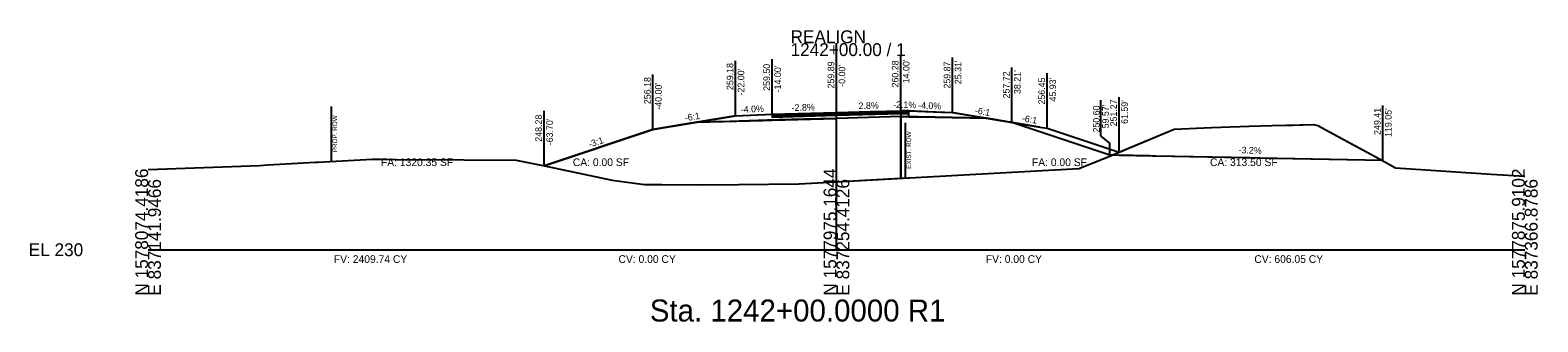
# Model space of a CAD drawing. Extents: x -26 to 6303, y -16 to 9563.
# Drawn here: x 1974.3 to 2302.8, y 1984.3 to 2047.8 of the extents above; entities that cross this region are included whole.
import ezdxf

# ---------------------------------------------------------------- set-up
doc = ezdxf.new("R2010")
doc.units = 0
for name, color, linetype in [('ASPHALT_19MM1', 7, 'Continuous'), ('ASPHALT_9_5MM1', 7, 'Continuous'), ('CONST_DCH', 7, 'Continuous'), ('CONST_LV3', 7, 'Continuous'), ('Draft_XS_Grid', 7, 'Continuous'), ('Draft_XS_Text', 7, 'Continuous'), ('DTM_P_FINISHED_GRADE', 7, 'Continuous'), ('DTM_P_FINISHED_GRADE2', 7, 'Continuous'), ('DTM_TEMP_DROP', 7, 'Continuous'), ('DTM_X_GROUND', 7, 'Continuous'), ('TRANS_EOP_PAVED', 7, 'Continuous'), ('TRANS_PAVED_SHOULDERS', 7, 'Continuous'), ('XS_CELL', 7, 'Continuous'), ('XS_M_SHAPES_EARTHWORK', 7, 'Continuous'), ('XS_P_ASPHALT', 7, 'Continuous'), ('XS_P_GROUND', 7, 'Continuous'), ('XS_P_ROW', 7, 'Continuous'), ('XS_P_SHOULDER', 7, 'Continuous'), ('XS_P_SUBGRADE_GRANULAR', 7, 'Continuous'), ('XS_P_TX_CLEARZONE', 7, 'Continuous'), ('XS_P_TX_FS_BS', 7, 'Continuous'), ('XS_SHEET_EW_TX_AREA', 7, 'Continuous'), ('XS_SHEET_EW_TX_VOLUME', 7, 'Continuous'), ('XS_X_ROW', 7, 'Continuous')]:
    doc.layers.add(name, color=color, linetype=linetype)

msp = doc.modelspace()

# ---------------------------------------------------------------- linework, layer by layer
at = {"layer": 'ASPHALT_19MM1'}
for points in [[(2136, 2029.17), (2136, 2028.9), (2150, 2029.29), (2150, 2029.29), (2164, 2029.68), (2164, 2029.68), (2164, 2029.95), (2164, 2029.95), (2164, 2029.95), (2150, 2029.56), (2150, 2029.56), (2136, 2029.17), (2136, 2029.17)], [(2164, 2029.95), (2164, 2029.95), (2164, 2029.68), (2164, 2029.68), (2165.76, 2029.64), (2165.76, 2029.92), (2164, 2029.95)]]:
    msp.add_lwpolyline(points, dxfattribs=at)
at = {"layer": 'ASPHALT_9_5MM1'}
for points in [[(2136, 2029.5), (2150, 2029.89), (2150, 2029.89), (2164, 2030.28), (2164, 2030.28), (2164, 2030.16), (2164, 2030.16), (2150, 2029.77), (2150, 2029.77), (2136, 2029.37), (2136, 2029.5)], [(2164, 2030.28), (2164, 2030.28), (2164, 2030.16), (2164, 2030.16), (2165.76, 2030.12), (2165.76, 2030.25), (2164, 2030.28)]]:
    msp.add_lwpolyline(points, dxfattribs=at)
at = {"layer": 'CONST_LV3'}
for points in [[(2119.53, 2027.77), (2110, 2026.18)], [(2150, 2029.89), (2150, 2029.89), (2157.57, 2030.1), (2157.57, 2030.1), (2164, 2030.28), (2165.76, 2030.25), (2165.76, 2030.25)], [(2164, 2030.28), (2164, 2030.28), (2164, 2029.01), (2164, 2029.01), (2165.76, 2028.98), (2165.76, 2030.25), (2164, 2030.28)], [(2175.45, 2029.85), (2175.45, 2029.85), (2169.95, 2030.07), (2169.95, 2030.07), (2168.47, 2030.14), (2168.47, 2030.14), (2165.76, 2030.25)]]:
    msp.add_lwpolyline(points, dxfattribs=at)
at = {"layer": 'DTM_P_FINISHED_GRADE'}
msp.add_lwpolyline([(2164, 2030.28), (2164, 2030.28), (2165.76, 2030.25)], dxfattribs=at)
at = {"layer": 'DTM_P_FINISHED_GRADE2'}
msp.add_lwpolyline([(2086.3, 2018.28), (2110, 2026.18), (2128, 2029.18), (2136, 2029.5), (2150, 2029.89), (2164, 2030.28), (2165.76, 2030.25), (2172.92, 2029.96), (2175.31, 2029.87)], dxfattribs=at)
at = {"layer": 'DTM_X_GROUND'}
msp.add_lwpolyline([(2000, 2017.45), (2024.27, 2018.37), (2026.11, 2018.5), (2036.38, 2019.08), (2037.04, 2019.09), (2048.82, 2019.71), (2050.57, 2019.71), (2054.1, 2019.69), (2068.83, 2019.59), (2080.19, 2019.52), (2086.41, 2018.26), (2101.1, 2015.12), (2107.05, 2014.38), (2108.23, 2014.21), (2111.94, 2014.19), (2120.83, 2014.15), (2128.63, 2014.21), (2141.83, 2014.36), (2141.86, 2014.36), (2167.22, 2015.76), (2202.81, 2017.73), (2209.24, 2020.27), (2223.57, 2026.27), (2231.75, 2026.61), (2239.92, 2026.94), (2244.92, 2027.06), (2253.93, 2027.28), (2254.89, 2027.03), (2268.34, 2019.82), (2271.81, 2017.83), (2292.68, 2016.47), (2300, 2015.99)], dxfattribs=at)
at = {"layer": 'TRANS_PAVED_SHOULDERS'}
for points in [[(2136, 2029.37), (2136, 2029.17), (2150, 2029.56), (2150, 2029.56), (2164, 2029.95), (2164, 2029.95), (2164, 2030.16), (2164, 2030.16), (2164, 2030.16), (2150, 2029.77), (2150, 2029.77), (2136, 2029.37), (2136, 2029.37)], [(2164, 2030.16), (2164, 2030.16), (2164, 2029.95), (2164, 2029.95), (2165.76, 2029.92), (2165.76, 2030.12), (2164, 2030.16)]]:
    msp.add_lwpolyline(points, dxfattribs=at)
at = {"layer": 'XS_CELL'}
for p, q in [((2150, 2000), (2150, 2045)), ((2000, 2000), (2150, 2000)), ((2150, 2000), (2300, 2000))]:
    msp.add_line(p, q, dxfattribs=at)
at = {"layer": 'XS_M_SHAPES_EARTHWORK'}
for points in [[(2086.3, 2018.28), (2086.41, 2018.26), (2101.1, 2015.12), (2107.05, 2014.38), (2108.23, 2014.21), (2111.94, 2014.19), (2120.83, 2014.15), (2128.63, 2014.21), (2141.83, 2014.36), (2141.86, 2014.36), (2164, 2015.58), (2164, 2029.01), (2150, 2028.62), (2143, 2028.43), (2137.54, 2028.27), (2136, 2028.23), (2135, 2028.2), (2126.76, 2027.97), (2119.53, 2027.77), (2110, 2026.18)], [(2164, 2029.01), (2164, 2015.58), (2167.22, 2015.76), (2202.81, 2017.73), (2209.24, 2020.27), (2210, 2020.59), (2209.57, 2020.6), (2188.21, 2027.72), (2194.31, 2026.72), (2182.73, 2028.64), (2175.25, 2028.79)]]:
    msp.add_lwpolyline(points, close=True, dxfattribs=at)
at = {"layer": 'XS_P_ASPHALT'}
msp.add_lwpolyline([(2165.76, 2030.25), (2164, 2030.28), (2164, 2030.28)], dxfattribs=at)
at = {"layer": 'XS_P_GROUND'}
for points in [[(2128, 2029.18), (2110, 2026.18), (2086.3, 2018.28)], [(2175.31, 2029.87), (2194.31, 2026.72), (2195.93, 2026.45), (2211.59, 2021.27)], [(2209.57, 2020.6), (2209.57, 2020.6), (2196.95, 2024.81), (2196.95, 2024.81), (2188.21, 2027.72), (2175.5, 2029.84), (2175.5, 2029.84), (2175.5, 2029.84), (2175.45, 2029.85)], [(2240.08, 2019.99), (2240.08, 2019.99), (2219.63, 2020.4), (2219.63, 2020.4), (2218.85, 2020.41), (2218.85, 2020.41), (2218.3, 2020.43), (2218.3, 2020.43), (2218.29, 2020.43), (2218.29, 2020.43), (2218.26, 2020.43), (2218.26, 2020.43), (2218.22, 2020.43), (2218.22, 2020.43), (2218.2, 2020.43), (2218.2, 2020.43), (2217.41, 2020.44), (2217.41, 2020.44), (2216.89, 2020.45), (2216.89, 2020.45), (2216.89, 2020.45), (2216.89, 2020.45), (2216.86, 2020.45), (2216.86, 2020.45), (2216.83, 2020.45), (2216.83, 2020.45), (2216.8, 2020.46), (2216.8, 2020.46), (2215.99, 2020.47), (2215.99, 2020.47), (2215.52, 2020.48), (2215.51, 2020.48), (2215.51, 2020.48), (2215.51, 2020.48), (2215.5, 2020.48), (2215.5, 2020.48), (2215.47, 2020.48), (2215.47, 2020.48), (2215.43, 2020.48), (2215.43, 2020.48), (2214.58, 2020.5), (2214.58, 2020.5), (2214.19, 2020.51), (2214.19, 2020.51), (2214.18, 2020.51), (2214.18, 2020.51), (2214.16, 2020.51), (2214.16, 2020.51), (2214.11, 2020.51), (2214.11, 2020.51), (2213.09, 2020.53), (2213.09, 2020.53), (2212.92, 2020.53), (2212.92, 2020.53), (2212.92, 2020.53), (2212.92, 2020.53), (2212.91, 2020.53), (2212.91, 2020.53), (2212.89, 2020.53), (2212.89, 2020.53), (2212.84, 2020.53), (2212.84, 2020.53), (2212.29, 2020.55), (2212.29, 2020.55), (2212.27, 2020.55), (2212.27, 2020.55), (2212.26, 2020.55), (2212.26, 2020.55), (2211.74, 2020.56), (2211.74, 2020.56), (2211.73, 2020.56), (2211.73, 2020.56), (2211.72, 2020.56), (2211.72, 2020.56), (2211.72, 2020.56), (2211.66, 2020.56), (2211.66, 2020.56), (2211.65, 2020.56), (2211.65, 2020.56), (2210.62, 2020.58), (2210.62, 2020.58), (2210.61, 2020.58), (2210.61, 2020.58), (2210.61, 2020.58), (2210.61, 2020.58), (2210.61, 2020.58), (2210.54, 2020.58), (2210.54, 2020.58), (2210.3, 2020.59), (2210.3, 2020.59), (2209.61, 2020.6), (2209.61, 2020.6), (2209.57, 2020.6), (2209.57, 2020.6)], [(2269.05, 2019.41), (2249.42, 2019.8), (2245.86, 2019.87), (2244.67, 2019.9), (2240.08, 2019.99)]]:
    msp.add_lwpolyline(points, dxfattribs=at)
at = {"layer": 'XS_P_ROW'}
msp.add_line((2040, 2019.24), (2040, 2031.24), dxfattribs=at)
at = {"layer": 'XS_P_SHOULDER'}
for points in [[(2128, 2029.18), (2136, 2029.5), (2136, 2029.5)], [(2165.76, 2030.25), (2175.31, 2029.87)]]:
    msp.add_lwpolyline(points, dxfattribs=at)
at = {"layer": 'XS_P_SUBGRADE_GRANULAR'}
for points in [[(2119.53, 2027.77), (2134, 2028.17), (2134, 2028.17), (2136, 2028.23), (2136, 2028.23)], [(2136, 2028.23), (2150, 2028.62), (2150, 2028.62)], [(2164, 2029.01), (2164, 2029.01), (2150, 2028.62)], [(2165.76, 2028.98), (2164, 2029.01), (2164, 2029.01)], [(2165.76, 2028.98), (2167.77, 2028.94), (2182.73, 2028.64)]]:
    msp.add_lwpolyline(points, dxfattribs=at)
at = {"layer": 'XS_P_TX_CLEARZONE'}
for p, q in [((2128, 2029.18), (2128, 2041.18)), ((2136, 2029.5), (2136, 2041.5)), ((2150, 2029.89), (2150, 2041.89)), ((2164, 2030.28), (2164, 2042.28)), ((2175.31, 2029.87), (2175.31, 2041.87)), ((2110, 2026.18), (2110, 2038.18)), ((2188.21, 2027.72), (2188.21, 2039.72)), ((2195.93, 2026.45), (2195.93, 2038.45)), ((2207.59, 2024.75), (2207.59, 2032.6)), ((2211.59, 2021.27), (2211.59, 2033.27)), ((2269.05, 2019.41), (2269.05, 2031.41)), ((2086.3, 2018.28), (2086.3, 2030.28)), ((2207.59, 2024.75), (2209.57, 2023.11)), ((2209.57, 2020.6), (2209.57, 2023.11))]:
    msp.add_line(p, q, dxfattribs=at)
at = {"layer": 'XS_P_TX_FS_BS'}
msp.add_lwpolyline([(2210.02, 2020.6), (2215.88, 2023.05), (2223.57, 2026.27), (2231.75, 2026.61), (2239.92, 2026.94), (2244.92, 2027.06), (2249.42, 2027.17), (2253.93, 2027.28), (2254.89, 2027.03), (2261.61, 2023.42), (2268.34, 2019.82), (2269.05, 2019.41), (2215.52, 2020.48)], close=True, dxfattribs=at)
at = {"layer": 'XS_X_ROW'}
msp.add_line((2165.08, 2015.64), (2165.08, 2027.64), dxfattribs=at)

# ---------------------------------------------------------------- texts
at = {"layer": 'CONST_DCH'}
for p in [(2163.92, 2030.16), (2135.92, 2029.38), (2149.92, 2029.77), (2209.49, 2020.48)]:
    msp.add_text('X', height=0.24, dxfattribs=at).set_placement(p)
at = {"layer": 'CONST_LV3'}
for p in [(2109.92, 2026.06), (2195.85, 2026.33)]:
    msp.add_text('X', height=0.24, dxfattribs=at).set_placement(p)
at = {"layer": 'Draft_XS_Grid'}
msp.add_text('-', height=0.0001, dxfattribs=at).set_placement((2000, 2000))
at = {"layer": 'Draft_XS_Text'}
msp.add_text('Sta. 1242+00.0000 R1', height=4.8, dxfattribs=at).set_placement((2109.33, 1984.35))
at = {"layer": 'DTM_TEMP_DROP'}
for p in [(2211.51, 2021.15), (2086.23, 2018.16)]:
    msp.add_text('X', height=0.24, dxfattribs=at).set_placement(p)
at = {"layer": 'TRANS_EOP_PAVED'}
for p in [(2175.37, 2029.73), (2188.13, 2027.6), (2211.51, 2021.15), (2086.23, 2018.16)]:
    msp.add_text('X', height=0.24, dxfattribs=at).set_placement(p)
at = {"layer": 'XS_CELL'}
for s, p in [('REALIGN', (2140, 2045)), ('1242+00.00 / 1', (2140, 2042.2)), ('EL 230', (1974, 1998.6))]:
    msp.add_text(s, height=2.8, dxfattribs=at).set_placement(p)
for s, p in [('N 1578074.4186', (2000, 1990)), ('N 1577975.1644', (2150, 1990)), ('N 1577875.9102', (2300, 1990)), ('E 837141.9466', (2002.8, 1990)), ('E 837254.4126', (2152.8, 1990)), ('E 837366.8786', (2302.8, 1990))]:
    msp.add_text(s, height=2.8, rotation=90, dxfattribs=at).set_placement(p)
at = {"layer": 'XS_P_ASPHALT'}
msp.add_text('X', height=0.24, dxfattribs=at).set_placement((2268.97, 2019.29))
at = {"layer": 'XS_P_ROW'}
msp.add_text('PROP. ROW', height=1, rotation=90, dxfattribs=at).set_placement((2041.2, 2021.24))
at = {"layer": 'XS_P_SUBGRADE_GRANULAR'}
for p in [(2165.68, 2030.13), (2127.92, 2029.06), (2175.23, 2029.75)]:
    msp.add_text('X', height=0.24, dxfattribs=at).set_placement(p)
at = {"layer": 'XS_P_TX_CLEARZONE'}
for s, p in [('259.18', (2127.52, 2034.79)), ('259.50', (2135.52, 2034.62)), ('259.89', (2149.52, 2035.13)), ('260.28', (2163.52, 2035.35)), ("14.00'", (2165.92, 2036.26)), ('259.87', (2174.83, 2035.11)), ("25.31'", (2177.23, 2036.07)), ('256.18', (2109.52, 2031.72)), ("-22.00'", (2129.92, 2033.61)), ("-14.00'", (2137.92, 2034.29)), ("-0.00'", (2151.92, 2035.5)), ('257.72', (2187.73, 2032.97)), ("38.21'", (2190.13, 2033.92)), ('256.45', (2195.45, 2031.63)), ("45.93'", (2197.85, 2032.29)), ("-40.00'", (2111.92, 2030.5)), ('250.60', (2207.35, 2025.54)), ("59.57'", (2209.34, 2026.44)), ('251.27', (2211.11, 2026.87)), ("61.59'", (2213.51, 2027.4)), ('249.41', (2268.57, 2025.02)), ("119.05'", (2270.97, 2024.57)), ('248.28', (2085.82, 2023.53)), ("-63.70'", (2088.22, 2022.76))]:
    msp.add_text(s, height=1.44, rotation=90, dxfattribs=at).set_placement(p)
at = {"layer": 'XS_P_TX_FS_BS'}
for s, rotation, p in [('-4.0%', 2.2906, (2129.18, 2029.83)), ('-2.8%', 1.6039, (2140.25, 2030.22)), ('2.8%', 1.6039, (2154.84, 2030.63)), ('-2.1%', 358.816, (2162.34, 2030.92)), ('-4.0%', 357.7307, (2167.77, 2030.77)), ('-6:1', 350.5377, (2180.1, 2029.68)), ('-6:1', 9.4642, (2117.08, 2027.97)), ('-6:1', 350.6907, (2190.34, 2027.98)), ('-3:1', 18.4332, (2096.24, 2022.23)), ('-3.2%', 358.1513, (2237.61, 2021.03))]:
    msp.add_text(s, height=1.44, rotation=rotation, dxfattribs=at).set_placement(p)
at = {"layer": 'XS_SHEET_EW_TX_AREA'}
for s, p in [('FA: 1320.35 SF', (2050.75, 2018.22)), ('CA: 0.00 SF', (2092.56, 2018.22)), ('FA: 0.00 SF', (2192.6, 2018.22)), ('CA: 313.50 SF', (2231.4, 2018.22))]:
    msp.add_text(s, height=1.68, dxfattribs=at).set_placement(p)
at = {"layer": 'XS_SHEET_EW_TX_VOLUME'}
for s, p in [('FV: 2409.74 CY', (2040.49, 1997.12)), ('CV: 0.00 CY', (2102.51, 1997.12)), ('FV: 0.00 CY', (2182.55, 1997.12)), ('CV: 606.05 CY', (2241.06, 1997.12))]:
    msp.add_text(s, height=1.68, dxfattribs=at).set_placement(p)
at = {"layer": 'XS_X_ROW'}
msp.add_text('EXIST. ROW', height=1, rotation=90, dxfattribs=at).set_placement((2166.28, 2017.64))

doc.saveas('drawing.dxf')
